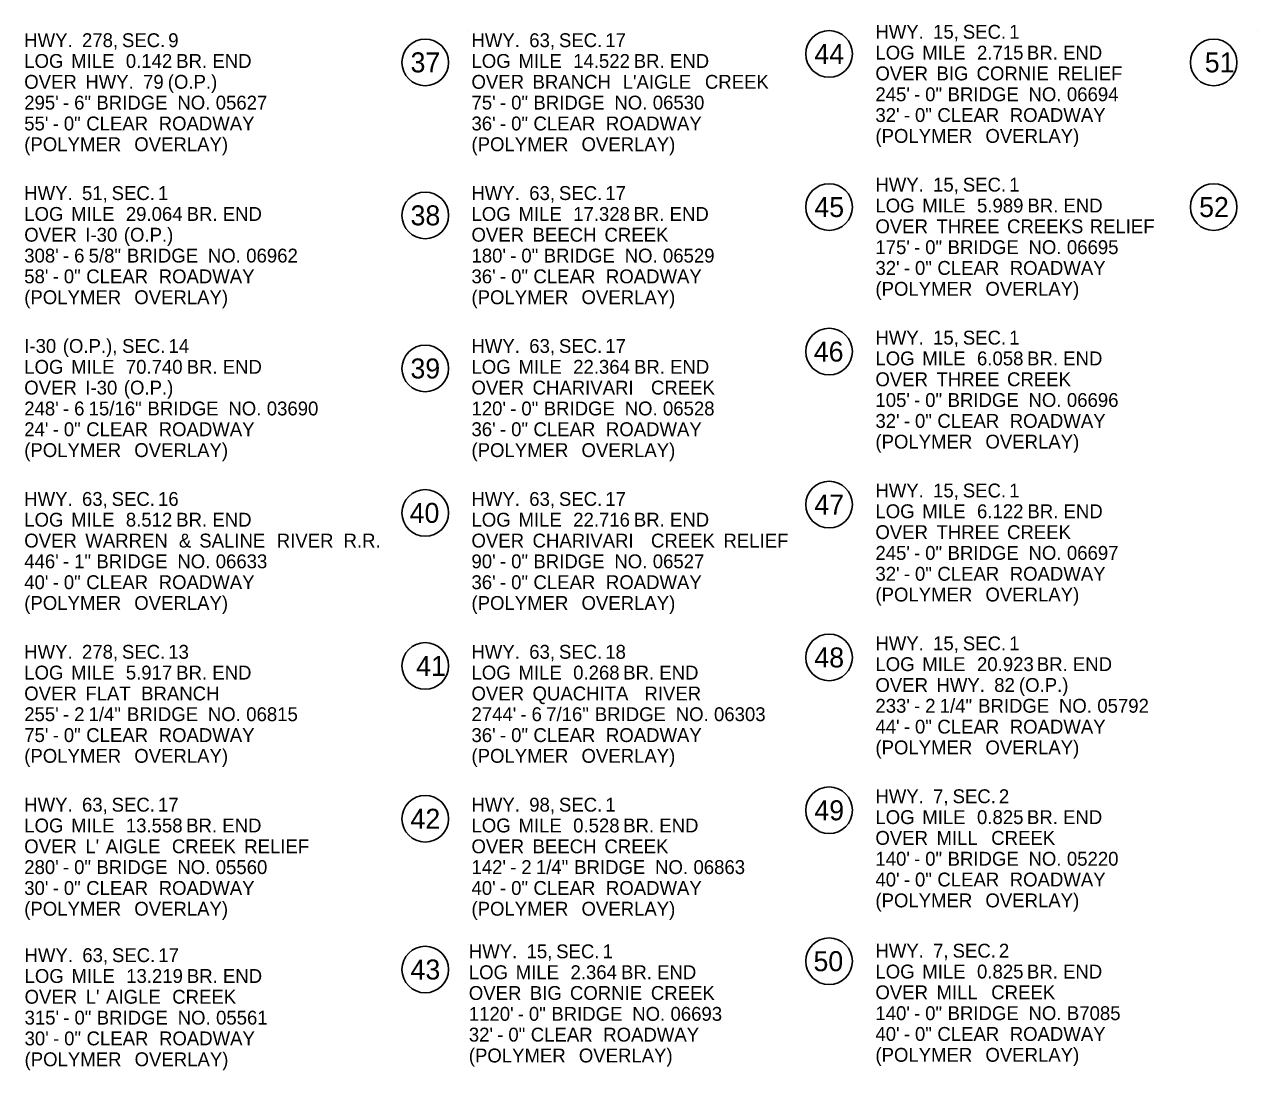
# Model space of a CAD drawing. Extents: x 3046 to 131673, y -8885 to 10756.
# Drawn here: x 100874 to 111982, y -8234 to 1185 of the extents above; entities that cross this region are included whole.
import ezdxf

# ---------------------------------------------------------------- set-up
doc = ezdxf.new("R2010")
doc.units = 0
for name, color, linetype in [('Default', 7, 'Continuous'), ('R_Annotation', 7, 'Continuous'), ('R_Border Notes', 7, 'Continuous')]:
    doc.layers.add(name, color=color, linetype=linetype)

msp = doc.modelspace()

# ---------------------------------------------------------------- linework, layer by layer
at = {"layer": 'R_Annotation'}
for centre in [(108122, 921), (104483, 845), (111588, 845), (104483, -533), (108122, -458), (111588, -458), (108122, -1760), (104483, -1912), (108122, -3138), (104483, -3213), (108122, -4515), (104483, -4591), (104483, -5968), (108122, -5892), (108122, -7251), (104483, -7326)]:
    msp.add_circle(centre, 210, dxfattribs=at)
at = {"layer": 'R_Border Notes'}
for p, q in [((104876, 1132), (104876, 1132)), ((111982, 1132), (111982, 1132)), ((104876, -7100), (104876, -7100)), ((108540, -7094), (108540, -7094))]:
    msp.add_line(p, q, dxfattribs=at)

# ---------------------------------------------------------------- texts
at = {"layer": 'Default'}
for s, p in [('HWY.', (108540, 1058)), (' 15,', (109013, 1058)), (' SEC.', (109281, 1058)), (' 1', (109699, 1058)), ('HWY.', (100870, 982)), (' 278,', (101344, 982)), (' SEC.', (101704, 982)), (' 9', (102121, 982)), ('HWY.', (104900, 982)), (' 63,', (105374, 982)), (' SEC.', (105642, 982)), (' 17', (106059, 982)), ('LOG', (100870, 795)), (' MILE', (101246, 795)), (' 0.142', (101739, 795)), (' BR.', (102193, 795)), (' END', (102519, 795)), ('LOG', (104900, 795)), (' MILE', (105277, 795)), (' 14.522', (105770, 795)), (' BR.', (106316, 795)), (' END', (106642, 795)), ('LOG', (108540, 870)), (' MILE', (108916, 870)), (' 2.715', (109409, 870)), (' BR.', (109859, 870)), (' END', (110184, 870)), ('OVER', (108540, 683)), (' BIG', (109044, 683)), (' CORNIE', (109405, 683)), (' RELIEF', (110134, 683)), ('OVER', (100870, 607)), (' HWY.', (101374, 607)), (' 79', (101894, 607)), (' (O.P.)', (102117, 607)), ('OVER', (104900, 607)), (' BRANCH', (105404, 607)), (" L'AIGLE", (106216, 607)), (' CREEK', (106957, 607)), ("245'", (108540, 495)), (' 0"', (108942, 495)), (' BRIDGE', (109144, 495)), (' NO.', (109873, 495)), (' 06694', (110219, 495)), ("295'", (100870, 420)), (' -', (101172, 420)), (' 6"', (101273, 420)), (' BRIDGE', (101474, 420)), (' NO.', (102203, 420)), (' 05627', (102549, 420)), ("75'", (104900, 420)), (' -', (105110, 420)), (' 0"', (105211, 420)), (' BRIDGE', (105412, 420)), (' NO.', (106141, 420)), (' 06530', (106487, 420)), (' -', (108842, 495)), ("55'", (100870, 232)), (' 0"', (101180, 232)), (' CLEAR', (101382, 232)), (' ROADWAY', (102035, 232)), ("36'", (104900, 232)), (' 0"', (105211, 232)), (' CLEAR', (105412, 232)), (' ROADWAY', (106065, 232)), ("32'", (108540, 308)), (' -', (108750, 308)), (' 0"', (108850, 308)), (' CLEAR', (109052, 308)), (' ROADWAY', (109704, 308)), (' -', (101080, 232)), (' -', (105110, 232)), ('(POLYMER', (108540, 120)), (' OVERLAY)', (109485, 120)), ('(POLYMER', (100870, 45)), (' OVERLAY)', (101815, 45)), ('(POLYMER', (104900, 45)), (' OVERLAY)', (105845, 45)), ('HWY.', (108540, -319)), (' 15,', (109013, -319)), (' SEC.', (109281, -319)), (' 1', (109699, -319)), ('HWY.', (100870, -395)), (' 51,', (101344, -395)), (' SEC.', (101611, -395)), (' 1', (102029, -395)), ('HWY.', (104900, -395)), (' 63,', (105374, -395)), (' SEC.', (105642, -395)), (' 17', (106059, -395)), ('LOG', (108540, -507)), (' MILE', (108916, -507)), (' 5.989', (109409, -507)), (' BR.', (109863, -507)), (' END', (110188, -507)), ('LOG', (100870, -583)), (' MILE', (101246, -583)), (' 29.064', (101739, -583)), (' BR.', (102287, -583)), (' END', (102612, -583)), ('LOG', (104900, -583)), (' MILE', (105277, -583)), (' 17.328', (105770, -583)), (' BR.', (106313, -583)), (' END', (106639, -583)), ('OVER', (100870, -770)), (' I-30', (101374, -770)), (' (O.P.)', (101721, -770)), ('OVER', (104900, -770)), (' BEECH', (105404, -770)), (' CREEK', (106052, -770)), ('OVER', (108540, -694)), (' THREE', (109044, -694)), (' CREEKS', (109680, -694)), (' RELIEF', (110424, -694)), ("175'", (108540, -882)), (' 0"', (108942, -882)), (' BRIDGE', (109144, -882)), (' NO.', (109873, -882)), (' 06695', (110219, -882)), ("308'", (100870, -958)), (' 6', (101273, -958)), (' 5/8"', (101404, -958)), (' BRIDGE', (101749, -958)), (' NO.', (102478, -958)), (' 06962', (102824, -958)), ("180'", (104900, -958)), (' 0"', (105303, -958)), (' BRIDGE', (105505, -958)), (' NO.', (106234, -958)), (' 06529', (106579, -958)), (' -', (108842, -882)), (' -', (101172, -958)), (' -', (105203, -958)), ("32'", (108540, -1069)), (' 0"', (108850, -1069)), (' CLEAR', (109052, -1069)), (' ROADWAY', (109704, -1069)), ("58'", (100870, -1145)), (' -', (101080, -1145)), (' 0"', (101180, -1145)), (' CLEAR', (101382, -1145)), (' ROADWAY', (102035, -1145)), ("36'", (104900, -1145)), (' -', (105110, -1145)), (' 0"', (105211, -1145)), (' CLEAR', (105412, -1145)), (' ROADWAY', (106065, -1145)), (' -', (108750, -1069)), ('(POLYMER', (100870, -1333)), (' OVERLAY)', (101815, -1333)), ('(POLYMER', (104900, -1333)), (' OVERLAY)', (105845, -1333)), ('(POLYMER', (108540, -1257)), (' OVERLAY)', (109485, -1257)), ('I-30', (100870, -1772)), (' (O.P.),', (101171, -1772)), (' SEC.', (101705, -1772)), (' 14', (102123, -1772)), ('HWY.', (104900, -1772)), (' 63,', (105374, -1772)), (' SEC.', (105642, -1772)), (' 17', (106059, -1772)), ('HWY.', (108540, -1697)), (' 15,', (109013, -1697)), (' SEC.', (109281, -1697)), (' 1', (109699, -1697)), ('LOG', (108540, -1884)), (' MILE', (108916, -1884)), (' 6.058', (109409, -1884)), (' BR.', (109860, -1884)), (' END', (110186, -1884)), ('LOG', (100870, -1960)), (' MILE', (101246, -1960)), (' 70.740', (101739, -1960)), (' BR.', (102287, -1960)), (' END', (102612, -1960)), ('LOG', (104900, -1960)), (' MILE', (105277, -1960)), (' 22.364', (105770, -1960)), (' BR.', (106318, -1960)), (' END', (106643, -1960)), ('OVER', (108540, -2072)), (' THREE', (109044, -2072)), (' CREEK', (109680, -2072)), ('OVER', (100870, -2147)), (' I-30', (101374, -2147)), (' (O.P.)', (101721, -2147)), ('OVER', (104900, -2147)), (' CHARIVARI', (105404, -2147)), (' CREEK', (106471, -2147)), ("248'", (100870, -2335)), (' 6', (101273, -2335)), (' 15/16"', (101404, -2335)), (' BRIDGE', (101934, -2335)), (' NO.', (102663, -2335)), (' 03690', (103009, -2335)), ("120'", (104900, -2335)), (' 0"', (105303, -2335)), (' BRIDGE', (105505, -2335)), (' NO.', (106234, -2335)), (' 06528', (106579, -2335)), ("105'", (108540, -2259)), (' -', (108842, -2259)), (' 0"', (108942, -2259)), (' BRIDGE', (109144, -2259)), (' NO.', (109873, -2259)), (' 06696', (110219, -2259)), (' -', (101172, -2335)), (' -', (105203, -2335)), ("32'", (108540, -2447)), (' 0"', (108850, -2447)), (' CLEAR', (109052, -2447)), (' ROADWAY', (109704, -2447)), ("24'", (100870, -2522)), (' 0"', (101180, -2522)), (' CLEAR', (101382, -2522)), (' ROADWAY', (102035, -2522)), ("36'", (104900, -2522)), (' 0"', (105211, -2522)), (' CLEAR', (105412, -2522)), (' ROADWAY', (106065, -2522)), (' -', (108750, -2447)), (' -', (101080, -2522)), (' -', (105110, -2522)), ('(POLYMER', (108540, -2634)), (' OVERLAY)', (109485, -2634)), ('(POLYMER', (100870, -2710)), (' OVERLAY)', (101815, -2710)), ('(POLYMER', (104900, -2710)), (' OVERLAY)', (105845, -2710)), ('HWY.', (108540, -3074)), (' 15,', (109013, -3074)), (' SEC.', (109281, -3074)), (' 1', (109699, -3074)), ('HWY.', (100870, -3150)), (' 63,', (101344, -3150)), (' SEC.', (101611, -3150)), (' 16', (102029, -3150)), ('HWY.', (104900, -3150)), (' 63,', (105374, -3150)), (' SEC.', (105642, -3150)), (' 17', (106059, -3150)), ('LOG', (100870, -3337)), (' MILE', (101246, -3337)), (' 8.512', (101739, -3337)), (' BR.', (102193, -3337)), (' END', (102519, -3337)), ('LOG', (104900, -3337)), (' MILE', (105277, -3337)), (' 22.716', (105770, -3337)), (' BR.', (106317, -3337)), (' END', (106642, -3337)), ('LOG', (108540, -3261)), (' MILE', (108916, -3261)), (' 6.122', (109409, -3261)), (' BR.', (109863, -3261)), (' END', (110189, -3261)), ('OVER', (108540, -3449)), (' THREE', (109044, -3449)), (' CREEK', (109680, -3449)), ('OVER', (100870, -3525)), (' WARREN', (101374, -3525)), (' &', (102217, -3525)), (' SALINE', (102401, -3525)), (' RIVER', (103099, -3525)), (' R.R.', (103701, -3525)), ('OVER', (104900, -3525)), (' CHARIVARI', (105404, -3525)), (' CREEK', (106471, -3525)), (' RELIEF', (107124, -3525)), ("245'", (108540, -3636)), (' 0"', (108942, -3636)), (' BRIDGE', (109144, -3636)), (' NO.', (109873, -3636)), (' 06697', (110219, -3636)), ("446'", (100870, -3712)), (' -', (101172, -3712)), (' 1"', (101273, -3712)), (' BRIDGE', (101474, -3712)), (' NO.', (102203, -3712)), (' 06633', (102549, -3712)), ("90'", (104900, -3712)), (' -', (105110, -3712)), (' 0"', (105211, -3712)), (' BRIDGE', (105412, -3712)), (' NO.', (106141, -3712)), (' 06527', (106487, -3712)), (' -', (108842, -3636)), ("40'", (100870, -3900)), (' 0"', (101180, -3900)), (' CLEAR', (101382, -3900)), (' ROADWAY', (102035, -3900)), ("36'", (104900, -3900)), (' 0"', (105211, -3900)), (' CLEAR', (105412, -3900)), (' ROADWAY', (106065, -3900)), ("32'", (108540, -3824)), (' -', (108750, -3824)), (' 0"', (108850, -3824)), (' CLEAR', (109052, -3824)), (' ROADWAY', (109704, -3824)), (' -', (101080, -3900)), (' -', (105110, -3900)), ('(POLYMER', (108540, -4011)), (' OVERLAY)', (109485, -4011)), ('(POLYMER', (100870, -4087)), (' OVERLAY)', (101815, -4087)), ('(POLYMER', (104900, -4087)), (' OVERLAY)', (105845, -4087)), ('HWY.', (108540, -4451)), (' 15,', (109013, -4451)), (' SEC.', (109281, -4451)), (' 1', (109699, -4451)), ('HWY.', (100870, -4527)), (' 278,', (101344, -4527)), (' SEC.', (101704, -4527)), (' 13', (102121, -4527)), ('HWY.', (104900, -4527)), (' 63,', (105374, -4527)), (' SEC.', (105642, -4527)), (' 18', (106059, -4527)), ('LOG', (108540, -4638)), (' MILE', (108916, -4638)), (' 20.923', (109409, -4638)), (' BR.', (109948, -4638)), (' END', (110273, -4638)), ('LOG', (100870, -4714)), (' MILE', (101246, -4714)), (' 5.917', (101739, -4714)), (' BR.', (102193, -4714)), (' END', (102518, -4714)), ('LOG', (104900, -4714)), (' MILE', (105277, -4714)), (' 0.268', (105770, -4714)), (' BR.', (106221, -4714)), (' END', (106546, -4714)), ('OVER', (100870, -4902)), (' BRANCH', (101877, -4902)), ('OVER', (104900, -4902)), (' QUACHITA', (105404, -4902)), ('OVER', (108540, -4826)), (' HWY.', (109044, -4826)), (' 82', (109564, -4826)), (' (O.P.)', (109787, -4826)), (' FLAT', (101374, -4902)), (' RIVER', (106412, -4902)), ("233'", (108540, -5013)), (' 2', (108942, -5013)), (' 1/4"', (109073, -5013)), (' BRIDGE', (109419, -5013)), (' NO.', (110147, -5013)), (' 05792', (110493, -5013)), ("255'", (100870, -5089)), (' 2', (101273, -5089)), (' 1/4"', (101403, -5089)), (' BRIDGE', (101749, -5089)), (' NO.', (102478, -5089)), (' 06815', (102824, -5089)), ("2744'", (104900, -5089)), (' 6', (105395, -5089)), (' 7/16"', (105527, -5089)), (' BRIDGE', (105965, -5089)), (' NO.', (106694, -5089)), (' 06303', (107039, -5089)), (' -', (108842, -5013)), (' -', (101172, -5089)), (' -', (105295, -5089)), ("44'", (108540, -5201)), (' 0"', (108850, -5201)), (' CLEAR', (109052, -5201)), (' ROADWAY', (109704, -5201)), ("75'", (100870, -5277)), (' 0"', (101180, -5277)), (' CLEAR', (101382, -5277)), (' ROADWAY', (102035, -5277)), ("36'", (104900, -5277)), (' 0"', (105211, -5277)), (' CLEAR', (105412, -5277)), (' ROADWAY', (106065, -5277)), (' -', (108750, -5201)), (' -', (101080, -5277)), (' -', (105110, -5277)), ('(POLYMER', (108540, -5388)), (' OVERLAY)', (109485, -5388)), ('(POLYMER', (100870, -5464)), (' OVERLAY)', (101815, -5464)), ('(POLYMER', (104900, -5464)), (' OVERLAY)', (105845, -5464)), ('HWY.', (108540, -5828)), (' 7,', (109013, -5828)), (' SEC.', (109189, -5828)), (' 2', (109606, -5828)), ('HWY.', (100870, -5904)), (' 63,', (101344, -5904)), (' SEC.', (101611, -5904)), (' 17', (102029, -5904)), ('HWY.', (104900, -5904)), (' 98,', (105374, -5904)), (' SEC.', (105642, -5904)), (' 1', (106059, -5904)), ('LOG', (100870, -6091)), (' MILE', (101246, -6091)), (' 13.558', (101739, -6091)), (' BR.', (102283, -6091)), (' END', (102608, -6091)), ('LOG', (104900, -6091)), (' MILE', (105277, -6091)), (' 0.528', (105770, -6091)), (' BR.', (106221, -6091)), (' END', (106546, -6091)), ('LOG', (108540, -6016)), (' MILE', (108916, -6016)), (' 0.825', (109409, -6016)), (' BR.', (109859, -6016)), (' END', (110184, -6016)), ('OVER', (108540, -6203)), (' MILL', (109044, -6203)), (' CREEK', (109537, -6203)), ('OVER', (100870, -6279)), (" L'", (101374, -6279)), (' AIGLE', (101558, -6279)), (' CREEK', (102154, -6279)), (' RELIEF', (102806, -6279)), ('OVER', (104900, -6279)), (' BEECH', (105404, -6279)), (' CREEK', (106052, -6279)), ("140'", (108540, -6391)), (' 0"', (108942, -6391)), (' BRIDGE', (109144, -6391)), (' NO.', (109873, -6391)), (' 05220', (110219, -6391)), ("280'", (100870, -6466)), (' -', (101172, -6466)), (' 0"', (101273, -6466)), (' BRIDGE', (101474, -6466)), (' NO.', (102203, -6466)), (' 05560', (102549, -6466)), ("142'", (104900, -6466)), (' -', (105203, -6466)), (' 2', (105303, -6466)), (' 1/4"', (105434, -6466)), (' BRIDGE', (105779, -6466)), (' NO.', (106508, -6466)), (' 06863', (106854, -6466)), (' -', (108842, -6391)), ("30'", (100870, -6654)), (' 0"', (101180, -6654)), (' CLEAR', (101382, -6654)), (' ROADWAY', (102035, -6654)), ("40'", (104900, -6654)), (' 0"', (105211, -6654)), (' CLEAR', (105412, -6654)), (' ROADWAY', (106065, -6654)), ("40'", (108540, -6578)), (' -', (108750, -6578)), (' 0"', (108850, -6578)), (' CLEAR', (109052, -6578)), (' ROADWAY', (109704, -6578)), (' -', (101080, -6654)), (' -', (105110, -6654)), ('(POLYMER', (108540, -6766)), (' OVERLAY)', (109485, -6766)), ('(POLYMER', (100870, -6841)), (' OVERLAY)', (101815, -6841)), ('(POLYMER', (104900, -6841)), (' OVERLAY)', (105845, -6841)), ('HWY.', (104876, -7225)), (' 15,', (105350, -7225)), (' SEC.', (105617, -7225)), (' 1', (106035, -7225)), ('HWY.', (108540, -7219)), (' 7,', (109013, -7219)), (' SEC.', (109189, -7219)), (' 2', (109606, -7219)), ('HWY.', (100873, -7259)), (' 63,', (101347, -7259)), (' SEC.', (101614, -7259)), (' 17', (102032, -7259)), ('LOG', (100873, -7447)), (' MILE', (101249, -7447)), (' 13.219', (101742, -7447)), (' BR.', (102289, -7447)), (' END', (102614, -7447)), ('LOG', (104876, -7413)), (' MILE', (105252, -7413)), (' 2.364', (105746, -7413)), (' BR.', (106201, -7413)), (' END', (106526, -7413)), ('LOG', (108540, -7407)), (' MILE', (108916, -7407)), (' 0.825', (109409, -7407)), (' BR.', (109859, -7407)), (' END', (110184, -7407)), ('OVER', (100873, -7634)), (" L'", (101377, -7634)), (' AIGLE', (101561, -7634)), (' CREEK', (102157, -7634)), ('OVER', (104876, -7600)), (' BIG', (105380, -7600)), (' CORNIE', (105741, -7600)), (' CREEK', (106470, -7600)), ('OVER', (108540, -7594)), (' MILL', (109044, -7594)), (' CREEK', (109537, -7594)), ("1120'", (104876, -7788)), (' 0"', (105371, -7788)), (' BRIDGE', (105573, -7788)), (' NO.', (106302, -7788)), (' 06693', (106647, -7788)), ("140'", (108540, -7782)), (' 0"', (108942, -7782)), (' BRIDGE', (109144, -7782)), (' NO.', (109873, -7782)), (' B7085', (110219, -7782)), ("315'", (100873, -7822)), (' -', (101175, -7822)), (' 0"', (101276, -7822)), (' BRIDGE', (101477, -7822)), (' NO.', (102206, -7822)), (' 05561', (102552, -7822)), (' -', (105271, -7788)), (' -', (108842, -7782)), ("30'", (100873, -8009)), (' 0"', (101183, -8009)), (' CLEAR', (101385, -8009)), (' ROADWAY', (102038, -8009)), ("32'", (104876, -7975)), (' 0"', (105186, -7975)), (' CLEAR', (105388, -7975)), (' ROADWAY', (106041, -7975)), ("40'", (108540, -7969)), (' 0"', (108850, -7969)), (' CLEAR', (109052, -7969)), (' ROADWAY', (109704, -7969)), (' -', (101083, -8009)), (' -', (105086, -7975)), (' -', (108750, -7969)), ('(POLYMER', (100873, -8197)), (' OVERLAY)', (101818, -8197)), ('(POLYMER', (104876, -8163)), (' OVERLAY)', (105821, -8163)), ('(POLYMER', (108540, -8157)), (' OVERLAY)', (109485, -8157))]:
    msp.add_text(s, height=125, rotation=360, dxfattribs=at).set_placement(p)
at = {"layer": 'R_Annotation'}
for s, p in [('44', (107990, 831)), ('37', (104351, 755)), ('51', (111508, 755)), ('38', (104351, -623)), ('45', (107990, -548)), ('52', (111457, -548)), ('46', (107985, -1850)), ('39', (104350, -2002)), ('47', (107990, -3228)), ('40', (104343, -3303)), ('48', (107990, -4605)), ('41', (104402, -4681)), ('42', (104351, -6058)), ('49', (107990, -5982)), ('50', (107982, -7341)), ('43', (104351, -7416))]:
    msp.add_text(s, height=180, dxfattribs=at).set_placement(p)

doc.saveas('drawing.dxf')
